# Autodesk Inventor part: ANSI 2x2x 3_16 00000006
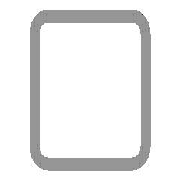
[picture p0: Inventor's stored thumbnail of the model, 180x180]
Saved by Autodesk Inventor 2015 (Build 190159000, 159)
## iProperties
_FrameMemberDoc: Frame Member File
_Version: 15.0.0
_CCFamilyMember: 1
_CCFamilyDisplayName: ANSI AISC (Square) - Tube
Created: 2007-02
Part Number: ANSI 2x2x 3_16 00000006
Material: Steel
Document SubType Name: Modeling
Standard: AISC
Designer: Autodesk, Inc.
Size Designation: 2x2x3/16
Stock Number: 2x2x 3/16
Density: 7.85 g/cm^3
Description: Tube
Standards Organization: ANSI
Language: en-US
Categories: <MemberInstance><Categories><Category DisplayName="Structural Shapes" InternalName="089c4875-fa83-4c05-b084-43b9cc11f5ed" Mnemonic="GRDR"><CategoryParameter Dis
Mass: 6274.61 g
Surface Area: 3376.79 cm^2
Volume: 799.314 cm^3
Appearance: Steel
IsCustomPart: 1
G_L: 38.465 in
G_W: 2.000 in
G_H: 2.000 in
+564C8632-C513-460F-986F-6275B3DCD282+CUTDETAIL1: Cut
Author: Autodesk, Inc.
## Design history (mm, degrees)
node "Start plane"
node "End plane"
sketch "Sketch"
  geometry: L1 (-25.4, -15.875)-(-25.4, 15.875); L2 (-15.875, 25.4)-(15.875, 25.4); L3 (25.4, 15.875)-(25.4, -15.875); L4 (15.875, -25.4)-(-15.875, -25.4); L5 (-15.875, 20.637)-(15.875, 20.638); L6 (20.637, 15.875)-(20.637, -15.875); L7 (15.875, -20.637)-(-15.875, -20.638); L8 (-20.637, -15.875)-(-20.637, 15.875); L9 (0, 38.322)-(0, -38.322) reference; L10 (-38.322, 0)-(38.322, 0) reference; A1 r 9.525 centre (-15.875, -15.875) between (-25.4, -15.875) and (-15.875, -25.4); A2 r 9.525 centre (-15.875, 15.875) between (-15.875, 25.4) and (-25.4, 15.875); A3 r 9.525 centre (15.875, 15.875) between (25.4, 15.875) and (15.875, 25.4); A4 r 9.525 centre (15.875, -15.875) between (15.875, -25.4) and (25.4, -15.875); A5 r 4.762 centre (-15.875, 15.875) between (-15.875, 20.637) and (-20.637, 15.875); A6 r 4.762 centre (15.875, 15.875) between (20.637, 15.875) and (15.875, 20.638); A7 r 4.762 centre (15.875, -15.875) between (15.875, -20.637) and (20.637, -15.875); A8 r 4.762 centre (-15.875, -15.875) between (-20.637, -15.875) and (-15.875, -20.638)
  constraints: 16 end point, 16 point on circle, 8 centre point, 8 tangent, 4 parallel, 3 equal radius, 2 perpendicular, 7 other
  dimensions: "d10" = 50.8 distance between parallel lines of L2 L4 (= G_H); "d11" = 50.8 distance between parallel lines of L1 L3 (= G_W); "d12" = 4.7625 distance between parallel lines of L3 L6 (= G_T); "d15" = 25.4 distance between parallel lines of L2 L10 (= 0.5 x d10); "d16" = 25.4 distance between parallel lines of L9 L3 (= 0.5 x d11); "d17" = 9.525 radius of A1 (= G_IR)
extrude "Body" new body sketch "Sketch" stored distance "d3" = 977 (= G_L); taper "d4" = 0 deg
node "Driven Length"
  sketch "Sketch4"
    geometry: L1 (0, 0)-(10, 0) reference
    constraints: 2 end point, 1 horizontal
  workplane "Work Plane4"
  sketch "Sketch5"
    geometry: L1 (-2, -76.2)-(12, -76.2) reference; L2 (-2, 900.8)-(12, 900.8) reference
    dimensions: "d26" = 977 distance between parallel lines of L1 L2 (derived)
workplane "Work Plane3"
split "Split1"
sketch "Sketch3"
  geometry: 10 further points
hole "Hole1" sketch "Sketch3" at (19.05, 957.95), (19.05, 754.75), (19.05, 551.55), (19.05, 348.35), (19.05, 145.15), (-457.2, 957.95), (-457.2, 754.75), (-457.2, 551.55), (-457.2, 348.35), (-457.2, 145.15) diameter "d18" = 4.9784; stored, may be unused: countersink angle "d22" = 82 deg, drill point angle "d24" = 0 deg; dims "d19" = 12.7, "d20" = 9.525, "d21" = 6.35, "d23" = 19.05
body "Solid1"
other parameters: "G_W" = 50.8 [user parameter; used in 1 equation term], "G_H" = 50.8 [user parameter; used in 1 equation term], "G_T" = 4.7625 [user parameter; used in 1 equation term], "G_IR" = 9.525 [user parameter; used in 1 equation term], "G_L" = 977 (= d26) [user parameter; used in 1 equation term], "G_OFFSET_START" = 76.2 [user parameter; used in 1 equation term], "G_OFFSET_END" = 0 [user parameter; used in 1 equation term], "d13" = -76.2 (= -G_OFFSET_START), "d14" = 900.8 (= G_OFFSET_END + B_L), "B_L" = 900.8 [user parameter; used in 1 equation term], "d25" = 90 deg
